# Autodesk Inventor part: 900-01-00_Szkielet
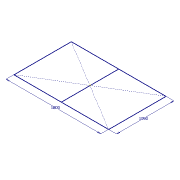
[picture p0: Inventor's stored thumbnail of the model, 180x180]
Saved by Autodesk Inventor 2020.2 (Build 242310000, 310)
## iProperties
Created: 2015-10
Part Number: 900-01-00_Szkielet
Material: Ogólny
Document SubType Name: Modeling
Designer: F.Stasiak
Density: 1 g/cm^3
Appearance: Domyślna
Catalog Web Link: www.expertbooks.pl
Manager: www.cadconsulting.pl
Company: Fabian Stasiak CAD Consulting
Author: F.Stasiak
Subject: Zbiór ćwiczeń. Autodesk Inventor 2020. Kurs Professional
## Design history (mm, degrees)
sketch "Szkic1"
  geometry: L1 (-900, 545)-(900, 545); L2 (900, 545)-(900, -545); L3 (900, -545)-(-900, -545); L4 (-900, -545)-(-900, 545); L5 (-900, 545)-(900, -545); L6 (900, 545)-(-900, -545); L7 (0, 545)-(0, -545); 1 further point
  constraints: 14 end point, 4 midpoint, 2 parallel, 1 horizontal, 1 perpendicular
  dimensions: "d0" = 1800 dimension on point (0, 0) L1.start L2.end L1.end L3.end L1 L2 L3 L4 L5 L6 L7.start L7.end L7; "d0" = 1800 distance of L2.end L3.end; "d1" = 1090 distance of L1.end L2.end
